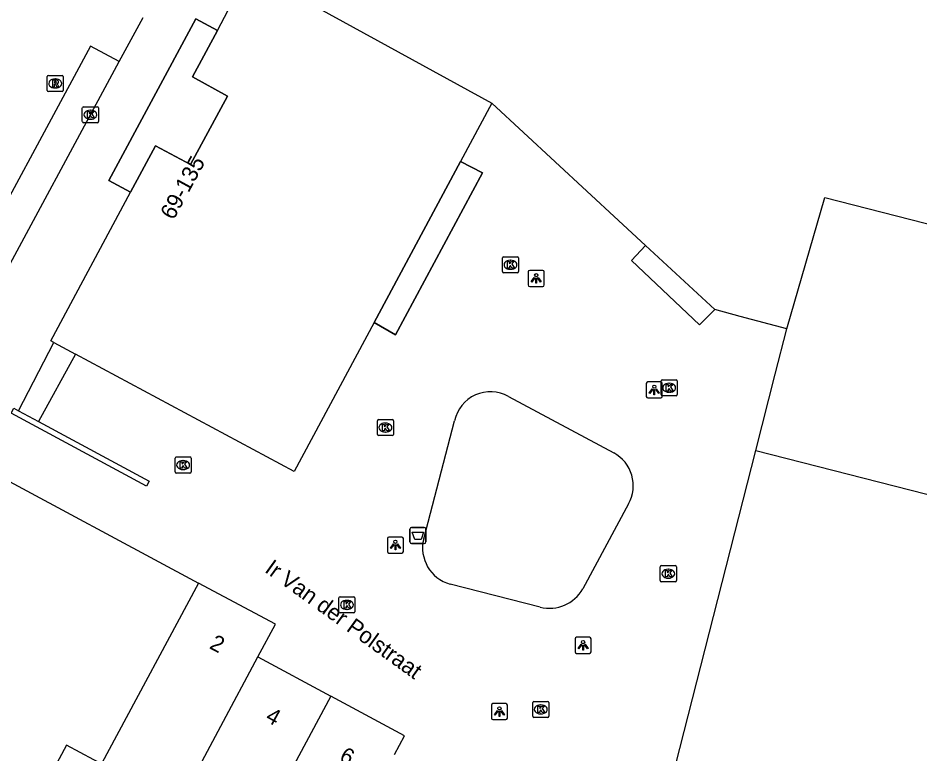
# Model space of a CAD drawing. Extents: x 159489 to 160304, y 383826 to 384530.
# Drawn here: x 159768.9 to 159824.9, y 384093.2 to 384138.9 of the extents above; entities that cross this region are included whole.
import ezdxf

# ---------------------------------------------------------------- set-up
doc = ezdxf.new("R2010")
doc.units = 0
for name, color, linetype in [('IMGEO_Afvalbak', 7, 'Continuous'), ('IMGEO_Kolk', 7, 'Continuous'), ('IMGEO_Lichtpunt', 7, 'Continuous'), ('IMGEO_Muur', 7, 'Continuous'), ('IMGEO_Openbare_ruimte_label', 7, 'Continuous'), ('IMGEO_Pand', 7, 'Continuous'), ('IMGEO_Pand_nummerreeks', 7, 'Continuous'), ('IMGEO_Pand_overbouw', 7, 'Continuous'), ('IMGEO_Rijbaan_lokaal_gesloten', 7, 'Continuous'), ('IMGEO_Rioolput', 7, 'Continuous'), ('IMGEO_Voetpad_open', 7, 'Continuous')]:
    doc.layers.add(name, color=color, linetype=linetype)

msp = doc.modelspace()

# ---------------------------------------------------------------- linework, layer by layer
at = {"layer": 'IMGEO_Afvalbak'}
for p, q in [((159793.2, 384106.378), (159793.2, 384107.178)), ((159793.2, 384107.178), (159793.2, 384106.378)), ((159793.3, 384107.278), (159794.09, 384107.278)), ((159794.09, 384107.278), (159793.3, 384107.278)), ((159794.19, 384107.178), (159794.19, 384106.378)), ((159794.19, 384106.378), (159794.19, 384107.178)), ((159794.09, 384106.278), (159793.3, 384106.278)), ((159793.3, 384106.278), (159794.09, 384106.278))]:
    msp.add_line(p, q, dxfattribs=at)
msp.add_lwpolyline([(159793.343, 384106.992), (159794.047, 384106.992), (159793.898, 384106.522), (159793.492, 384106.522), (159793.343, 384106.992)], dxfattribs=at)
for centre, start, end in [((159793.3, 384107.178), 90, 180), ((159793.3, 384107.178), 90, 180), ((159794.09, 384107.178), 0, 90), ((159794.09, 384107.178), 360, 90), ((159793.3, 384106.378), 180, 270), ((159793.3, 384106.378), 180, 270), ((159794.09, 384106.378), 270, 0), ((159794.09, 384106.378), 270, 0)]:
    msp.add_arc(centre, 0.1, start, end, dxfattribs=at)
at = {"layer": 'IMGEO_Kolk'}
for p, q in [((159772.86, 384132.46), (159772.86, 384133.312)), ((159772.935, 384133.386), (159773.787, 384133.386)), ((159773.861, 384133.312), (159773.861, 384132.46)), ((159773.348, 384133.166), (159773.373, 384133.166)), ((159773.787, 384132.386), (159772.935, 384132.386)), ((159773.371, 384132.606), (159773.346, 384132.606)), ((159798.939, 384123.15), (159798.939, 384124.002)), ((159799.014, 384124.076), (159799.866, 384124.076)), ((159799.427, 384123.856), (159799.452, 384123.856)), ((159799.94, 384124.002), (159799.94, 384123.15)), ((159799.45, 384123.296), (159799.425, 384123.296)), ((159799.866, 384123.076), (159799.014, 384123.076)), ((159808.791, 384115.518), (159808.791, 384116.37)), ((159808.866, 384116.444), (159809.718, 384116.444)), ((159809.279, 384116.224), (159809.304, 384116.224)), ((159809.792, 384116.37), (159809.792, 384115.518)), ((159809.718, 384115.444), (159808.866, 384115.444)), ((159809.302, 384115.664), (159809.277, 384115.664)), ((159791.175, 384113.049), (159791.175, 384113.901)), ((159791.25, 384113.975), (159792.102, 384113.975)), ((159791.663, 384113.755), (159791.688, 384113.755)), ((159792.176, 384113.901), (159792.176, 384113.049)), ((159791.686, 384113.195), (159791.661, 384113.195)), ((159792.102, 384112.975), (159791.25, 384112.975)), ((159778.616, 384110.723), (159778.616, 384111.575)), ((159778.691, 384111.649), (159779.543, 384111.649)), ((159779.104, 384111.429), (159779.129, 384111.429)), ((159779.617, 384111.575), (159779.617, 384110.723)), ((159779.127, 384110.869), (159779.102, 384110.869)), ((159779.543, 384110.649), (159778.691, 384110.649)), ((159808.737, 384103.981), (159808.737, 384104.833)), ((159808.812, 384104.907), (159809.664, 384104.907)), ((159809.738, 384104.833), (159809.738, 384103.981)), ((159809.225, 384104.687), (159809.25, 384104.687)), ((159809.664, 384103.907), (159808.812, 384103.907)), ((159809.248, 384104.127), (159809.223, 384104.127)), ((159788.785, 384102.048), (159788.785, 384102.9)), ((159788.86, 384102.974), (159789.712, 384102.974)), ((159789.273, 384102.754), (159789.298, 384102.754)), ((159789.786, 384102.9), (159789.786, 384102.048)), ((159789.712, 384101.974), (159788.86, 384101.974)), ((159789.296, 384102.194), (159789.271, 384102.194)), ((159800.819, 384095.561), (159800.819, 384096.413)), ((159800.894, 384096.487), (159801.746, 384096.487)), ((159801.82, 384096.413), (159801.82, 384095.561)), ((159801.307, 384096.267), (159801.332, 384096.267)), ((159801.746, 384095.487), (159800.894, 384095.487)), ((159801.33, 384095.707), (159801.305, 384095.707))]:
    msp.add_line(p, q, dxfattribs=at)
for points in [[(159772.86, 384132.46), (159772.86, 384133.312)], [(159772.935, 384133.386), (159773.787, 384133.386)], [(159773.861, 384133.312), (159773.861, 384132.46)], [(159773.181, 384133.086), (159773.304, 384133.086), (159773.304, 384132.935), (159773.434, 384133.086), (159773.598, 384133.086), (159773.452, 384132.935), (159773.605, 384132.686), (159773.453, 384132.686), (159773.368, 384132.85), (159773.304, 384132.783), (159773.304, 384132.686), (159773.181, 384132.686), (159773.181, 384133.086)], [(159773.787, 384132.386), (159772.935, 384132.386)], [(159798.939, 384123.15), (159798.939, 384124.002)], [(159799.014, 384124.076), (159799.866, 384124.076)], [(159799.26, 384123.776), (159799.383, 384123.776), (159799.383, 384123.625), (159799.513, 384123.776), (159799.677, 384123.776), (159799.531, 384123.625), (159799.684, 384123.376), (159799.532, 384123.376), (159799.447, 384123.54), (159799.383, 384123.473), (159799.383, 384123.376), (159799.26, 384123.376), (159799.26, 384123.776)], [(159799.94, 384124.002), (159799.94, 384123.15)], [(159799.866, 384123.076), (159799.014, 384123.076)], [(159808.791, 384115.518), (159808.791, 384116.37)], [(159808.866, 384116.444), (159809.718, 384116.444)], [(159809.112, 384116.144), (159809.235, 384116.144), (159809.235, 384115.993), (159809.365, 384116.144), (159809.529, 384116.144), (159809.383, 384115.993), (159809.536, 384115.744), (159809.384, 384115.744), (159809.299, 384115.908), (159809.235, 384115.841), (159809.235, 384115.744), (159809.112, 384115.744), (159809.112, 384116.144)], [(159809.792, 384116.37), (159809.792, 384115.518)], [(159809.718, 384115.444), (159808.866, 384115.444)], [(159791.175, 384113.049), (159791.175, 384113.901)], [(159791.25, 384113.975), (159792.102, 384113.975)], [(159791.496, 384113.675), (159791.619, 384113.675), (159791.619, 384113.524), (159791.749, 384113.675), (159791.913, 384113.675), (159791.767, 384113.524), (159791.92, 384113.275), (159791.768, 384113.275), (159791.683, 384113.439), (159791.619, 384113.372), (159791.619, 384113.275), (159791.496, 384113.275), (159791.496, 384113.675)], [(159792.176, 384113.901), (159792.176, 384113.049)], [(159792.102, 384112.975), (159791.25, 384112.975)], [(159778.616, 384110.723), (159778.616, 384111.575)], [(159778.691, 384111.649), (159779.543, 384111.649)], [(159779.617, 384111.575), (159779.617, 384110.723)], [(159778.937, 384111.349), (159779.06, 384111.349), (159779.06, 384111.198), (159779.19, 384111.349), (159779.354, 384111.349), (159779.208, 384111.198), (159779.361, 384110.949), (159779.209, 384110.949), (159779.124, 384111.113), (159779.06, 384111.046), (159779.06, 384110.949), (159778.937, 384110.949), (159778.937, 384111.349)], [(159779.543, 384110.649), (159778.691, 384110.649)], [(159808.737, 384103.981), (159808.737, 384104.833)], [(159808.812, 384104.907), (159809.664, 384104.907)], [(159809.738, 384104.833), (159809.738, 384103.981)], [(159809.058, 384104.607), (159809.181, 384104.607), (159809.181, 384104.456), (159809.311, 384104.607), (159809.475, 384104.607), (159809.329, 384104.456), (159809.482, 384104.207), (159809.33, 384104.207), (159809.245, 384104.371), (159809.181, 384104.304), (159809.181, 384104.207), (159809.058, 384104.207), (159809.058, 384104.607)], [(159809.664, 384103.907), (159808.812, 384103.907)], [(159788.785, 384102.048), (159788.785, 384102.9)], [(159788.86, 384102.974), (159789.712, 384102.974)], [(159789.106, 384102.674), (159789.229, 384102.674), (159789.229, 384102.523), (159789.359, 384102.674), (159789.523, 384102.674), (159789.377, 384102.523), (159789.53, 384102.274), (159789.378, 384102.274), (159789.293, 384102.438), (159789.229, 384102.371), (159789.229, 384102.274), (159789.106, 384102.274), (159789.106, 384102.674)], [(159789.786, 384102.9), (159789.786, 384102.048)], [(159789.712, 384101.974), (159788.86, 384101.974)], [(159800.819, 384095.561), (159800.819, 384096.413)], [(159800.894, 384096.487), (159801.746, 384096.487)], [(159801.82, 384096.413), (159801.82, 384095.561)], [(159801.14, 384096.187), (159801.263, 384096.187), (159801.263, 384096.036), (159801.393, 384096.187), (159801.557, 384096.187), (159801.411, 384096.036), (159801.564, 384095.787), (159801.412, 384095.787), (159801.327, 384095.951), (159801.263, 384095.884), (159801.263, 384095.787), (159801.14, 384095.787), (159801.14, 384096.187)], [(159801.746, 384095.487), (159800.894, 384095.487)]]:
    msp.add_lwpolyline(points, dxfattribs=at)
for centre, start, end in [((159772.937, 384133.31), 91.552, 178.448), ((159772.937, 384133.31), 91.552, 178.448), ((159773.785, 384133.31), 1.552, 88.448), ((159773.785, 384133.31), 1.552, 88.448), ((159772.937, 384132.462), 181.552, 268.448), ((159772.937, 384132.462), 181.552, 268.448), ((159773.785, 384132.462), 271.552, 358.448), ((159773.785, 384132.462), 271.552, 358.448), ((159799.016, 384124), 91.552, 178.448), ((159799.016, 384124), 91.552, 178.448), ((159799.864, 384124), 1.552, 88.448), ((159799.864, 384124), 1.552, 88.448), ((159799.016, 384123.152), 181.552, 268.448), ((159799.016, 384123.152), 181.552, 268.448), ((159799.864, 384123.152), 271.552, 358.448), ((159799.864, 384123.152), 271.552, 358.448), ((159808.868, 384116.368), 91.552, 178.448), ((159808.868, 384116.368), 91.552, 178.448), ((159809.716, 384116.368), 1.552, 88.448), ((159809.716, 384116.368), 1.552, 88.448), ((159808.868, 384115.52), 181.552, 268.448), ((159808.868, 384115.52), 181.552, 268.448), ((159809.716, 384115.52), 271.552, 358.448), ((159809.716, 384115.52), 271.552, 358.448), ((159791.252, 384113.899), 91.552, 178.448), ((159791.252, 384113.899), 91.552, 178.448), ((159792.1, 384113.899), 1.552, 88.448), ((159792.1, 384113.899), 1.552, 88.448), ((159791.252, 384113.051), 181.552, 268.448), ((159791.252, 384113.051), 181.552, 268.448), ((159792.1, 384113.051), 271.552, 358.448), ((159792.1, 384113.051), 271.552, 358.448), ((159778.693, 384111.573), 91.552, 178.448), ((159778.693, 384111.573), 91.552, 178.448), ((159779.541, 384111.573), 1.552, 88.448), ((159779.541, 384111.573), 1.552, 88.448), ((159778.693, 384110.725), 181.552, 268.448), ((159778.693, 384110.725), 181.552, 268.448), ((159779.541, 384110.725), 271.552, 358.448), ((159779.541, 384110.725), 271.552, 358.448), ((159808.814, 384104.831), 91.552, 178.448), ((159808.814, 384104.831), 91.552, 178.448), ((159809.662, 384104.831), 1.552, 88.448), ((159809.662, 384104.831), 1.552, 88.448), ((159808.814, 384103.983), 181.552, 268.448), ((159808.814, 384103.983), 181.552, 268.448), ((159809.662, 384103.983), 271.552, 358.448), ((159809.662, 384103.983), 271.552, 358.448), ((159788.862, 384102.898), 91.552, 178.448), ((159788.862, 384102.898), 91.552, 178.448), ((159789.71, 384102.898), 1.552, 88.448), ((159789.71, 384102.898), 1.552, 88.448), ((159788.862, 384102.05), 181.552, 268.448), ((159788.862, 384102.05), 181.552, 268.448), ((159789.71, 384102.05), 271.552, 358.448), ((159789.71, 384102.05), 271.552, 358.448), ((159800.896, 384096.411), 91.552, 178.448), ((159800.896, 384096.411), 91.552, 178.448), ((159801.744, 384096.411), 1.552, 88.448), ((159801.744, 384096.411), 1.552, 88.448), ((159800.896, 384095.563), 181.552, 268.448), ((159800.896, 384095.563), 181.552, 268.448), ((159801.744, 384095.563), 271.552, 358.448), ((159801.744, 384095.563), 271.552, 358.448)]:
    msp.add_arc(centre, 0.0765, start, end, dxfattribs=at)
for centre, major_axis, ratio, start_param, end_param in [((159773.347, 384132.886), (-0.387, 0.002), 0.722429, 4.712389, 7.853982), ((159773.372, 384132.886), (-0.39, 0.002), 0.717154, 1.570796, 4.712389), ((159799.426, 384123.576), (-0.387, 0.002), 0.722429, 4.712389, 7.853982), ((159799.451, 384123.576), (-0.39, 0.002), 0.717154, 1.570796, 4.712389), ((159809.278, 384115.944), (-0.387, 0.002), 0.722429, 4.712389, 7.853982), ((159809.303, 384115.944), (-0.39, 0.002), 0.717154, 1.570796, 4.712389), ((159791.662, 384113.475), (-0.387, 0.002), 0.722429, 4.712389, 7.853982), ((159791.687, 384113.475), (-0.39, 0.002), 0.717154, 1.570796, 4.712389), ((159779.103, 384111.149), (-0.387, 0.002), 0.722429, 4.712389, 7.853982), ((159779.128, 384111.149), (-0.39, 0.002), 0.717154, 1.570796, 4.712389), ((159809.224, 384104.407), (-0.387, 0.002), 0.722429, 4.712389, 7.853982), ((159809.249, 384104.407), (-0.39, 0.002), 0.717154, 1.570796, 4.712389), ((159789.272, 384102.474), (-0.387, 0.002), 0.722429, 4.712389, 7.853982), ((159789.297, 384102.474), (-0.39, 0.002), 0.717154, 1.570796, 4.712389), ((159801.306, 384095.987), (-0.387, 0.002), 0.722429, 4.712389, 7.853982), ((159801.331, 384095.987), (-0.39, 0.002), 0.717154, 1.570796, 4.712389)]:
    msp.add_ellipse(centre, major_axis=major_axis, ratio=ratio, start_param=start_param, end_param=end_param, dxfattribs=at)
at = {"layer": 'IMGEO_Lichtpunt'}
for p, q in [((159801.44, 384123.228), (159800.632, 384123.228)), ((159801.44, 384123.228), (159800.632, 384123.228)), ((159800.538, 384123.133), (159800.538, 384122.326)), ((159800.538, 384123.133), (159800.538, 384122.326)), ((159801.534, 384122.326), (159801.534, 384123.133)), ((159801.534, 384122.326), (159801.534, 384123.133)), ((159800.632, 384122.232), (159801.44, 384122.232)), ((159800.632, 384122.232), (159801.44, 384122.232)), ((159807.867, 384116.215), (159807.867, 384115.408)), ((159807.867, 384116.215), (159807.867, 384115.408)), ((159808.769, 384116.31), (159807.961, 384116.31)), ((159808.769, 384116.31), (159807.961, 384116.31)), ((159808.863, 384115.408), (159808.863, 384116.215)), ((159808.863, 384115.408), (159808.863, 384116.215)), ((159807.961, 384115.314), (159808.769, 384115.314)), ((159807.961, 384115.314), (159808.769, 384115.314)), ((159791.796, 384106.589), (159791.796, 384105.782)), ((159791.796, 384106.589), (159791.796, 384105.782)), ((159792.698, 384106.684), (159791.89, 384106.684)), ((159792.698, 384106.684), (159791.89, 384106.684)), ((159792.792, 384105.782), (159792.792, 384106.589)), ((159792.792, 384105.782), (159792.792, 384106.589)), ((159791.89, 384105.688), (159792.698, 384105.688)), ((159791.89, 384105.688), (159792.698, 384105.688)), ((159803.447, 384100.366), (159803.447, 384099.559)), ((159803.447, 384100.366), (159803.447, 384099.559)), ((159804.349, 384100.461), (159803.541, 384100.461)), ((159804.349, 384100.461), (159803.541, 384100.461)), ((159804.443, 384099.559), (159804.443, 384100.366)), ((159804.443, 384099.559), (159804.443, 384100.366)), ((159803.541, 384099.465), (159804.349, 384099.465)), ((159803.541, 384099.465), (159804.349, 384099.465)), ((159799.155, 384096.35), (159798.347, 384096.35)), ((159799.155, 384096.35), (159798.347, 384096.35)), ((159798.253, 384096.255), (159798.253, 384095.448)), ((159798.253, 384096.255), (159798.253, 384095.448)), ((159799.249, 384095.448), (159799.249, 384096.255)), ((159799.249, 384095.448), (159799.249, 384096.255)), ((159798.347, 384095.354), (159799.155, 384095.354)), ((159798.347, 384095.354), (159799.155, 384095.354))]:
    msp.add_line(p, q, dxfattribs=at)
for points in [[(159800.912, 384122.797), (159800.951, 384122.769), (159800.763, 384122.507), (159800.725, 384122.534), (159800.912, 384122.797)], [(159801.014, 384122.749), (159801.061, 384122.749), (159801.061, 384122.427), (159801.014, 384122.427), (159801.014, 384122.749)], [(159801.124, 384122.769), (159801.162, 384122.796), (159801.349, 384122.534), (159801.31, 384122.506), (159801.124, 384122.769)], [(159808.241, 384115.879), (159808.28, 384115.851), (159808.092, 384115.589), (159808.054, 384115.616), (159808.241, 384115.879)], [(159808.343, 384115.831), (159808.39, 384115.831), (159808.39, 384115.509), (159808.343, 384115.509), (159808.343, 384115.831)], [(159808.453, 384115.851), (159808.491, 384115.878), (159808.678, 384115.616), (159808.639, 384115.588), (159808.453, 384115.851)], [(159792.17, 384106.253), (159792.209, 384106.225), (159792.021, 384105.963), (159791.983, 384105.99), (159792.17, 384106.253)], [(159792.272, 384106.205), (159792.319, 384106.205), (159792.319, 384105.883), (159792.272, 384105.883), (159792.272, 384106.205)], [(159792.382, 384106.225), (159792.42, 384106.252), (159792.607, 384105.99), (159792.568, 384105.962), (159792.382, 384106.225)], [(159803.821, 384100.03), (159803.86, 384100.002), (159803.672, 384099.74), (159803.634, 384099.767), (159803.821, 384100.03)], [(159803.923, 384099.982), (159803.97, 384099.982), (159803.97, 384099.66), (159803.923, 384099.66), (159803.923, 384099.982)], [(159804.033, 384100.002), (159804.071, 384100.029), (159804.258, 384099.767), (159804.219, 384099.739), (159804.033, 384100.002)], [(159798.627, 384095.919), (159798.666, 384095.891), (159798.478, 384095.629), (159798.44, 384095.656), (159798.627, 384095.919)], [(159798.729, 384095.871), (159798.776, 384095.871), (159798.776, 384095.549), (159798.729, 384095.549), (159798.729, 384095.871)], [(159798.839, 384095.891), (159798.877, 384095.918), (159799.064, 384095.656), (159799.025, 384095.628), (159798.839, 384095.891)]]:
    msp.add_lwpolyline(points, dxfattribs=at)
for centre in [(159801.037, 384122.931), (159808.366, 384116.013), (159792.295, 384106.387), (159803.946, 384100.164), (159798.752, 384096.053)]:
    msp.add_circle(centre, 0.0994, dxfattribs=at)
for centre, start, end in [((159800.632, 384123.133), 90, 180), ((159800.632, 384123.133), 90, 180), ((159801.44, 384123.133), 0, 90), ((159801.44, 384123.133), 0, 90), ((159800.632, 384122.326), 180, 270), ((159800.632, 384122.326), 180, 270), ((159801.44, 384122.326), 270, 0), ((159801.44, 384122.326), 270, 360), ((159807.961, 384116.215), 90, 180), ((159807.961, 384116.215), 90, 180), ((159808.769, 384116.215), 0, 90), ((159808.769, 384116.215), 0, 90), ((159807.961, 384115.408), 180, 270), ((159807.961, 384115.408), 180, 270), ((159808.769, 384115.408), 270, 0), ((159808.769, 384115.408), 270, 360), ((159791.89, 384106.589), 90, 180), ((159791.89, 384106.589), 90, 180), ((159792.698, 384106.589), 0, 90), ((159792.698, 384106.589), 0, 90), ((159791.89, 384105.782), 180, 270), ((159791.89, 384105.782), 180, 270), ((159792.698, 384105.782), 270, 0), ((159792.698, 384105.782), 270, 360), ((159803.541, 384100.366), 90, 180), ((159803.541, 384100.366), 90, 180), ((159804.349, 384100.366), 0, 90), ((159804.349, 384100.366), 0, 90), ((159803.541, 384099.559), 180, 270), ((159803.541, 384099.559), 180, 270), ((159804.349, 384099.559), 270, 0), ((159804.349, 384099.559), 270, 360), ((159798.347, 384096.255), 90, 180), ((159798.347, 384096.255), 90, 180), ((159799.155, 384096.255), 0, 90), ((159799.155, 384096.255), 0, 90), ((159798.347, 384095.448), 180, 270), ((159798.347, 384095.448), 180, 270), ((159799.155, 384095.448), 270, 0), ((159799.155, 384095.448), 270, 360)]:
    msp.add_arc(centre, 0.0946, start, end, dxfattribs=at)
at = {"layer": 'IMGEO_Muur'}
for points in [[(159768.446, 384114.365), (159768.611, 384114.673), (159768.906, 384114.514)], [(159770.147, 384113.845), (159777.002, 384110.151), (159776.835, 384109.843), (159768.446, 384114.365)], [(159768.906, 384114.514), (159770.147, 384113.845)]]:
    msp.add_lwpolyline(points, dxfattribs=at)
at = {"layer": 'IMGEO_Pand'}
for points in [[(159781.249, 384138.115), (159783.227, 384141.884)], [(159783.227, 384141.884), (159798.285, 384133.608)], [(159781.249, 384138.115), (159779.704, 384135.243), (159781.88, 384134.044), (159779.568, 384129.802), (159777.398, 384130.962), (159775.853, 384128.086)], [(159798.285, 384133.608), (159796.346, 384129.995)], [(159807.826, 384124.77), (159806.143, 384126.329), (159798.285, 384133.608)], [(159790.975, 384119.986), (159796.346, 384129.995)], [(159771.098, 384118.744), (159770.9, 384118.851), (159775.853, 384128.086)], [(159816.6, 384119.612), (159818.956, 384127.743), (159834.974, 384123.654)], [(159807.826, 384124.77), (159812.12, 384120.793)], [(159816.6, 384119.612), (159813.7, 384120.358), (159812.12, 384120.793)], [(159790.975, 384119.986), (159786.016, 384110.746), (159772.445, 384118.022)], [(159814.676, 384112.061), (159815.881, 384116.79), (159816.6, 384119.612)], [(159771.098, 384118.744), (159772.445, 384118.022)], [(159815.417, 384087.11), (159809.159, 384090.473), (159814.676, 384112.061)], [(159814.676, 384112.061), (159830.962, 384107.902)], [(159766.66, 384111.026), (159780.079, 384103.825)], [(159780.079, 384103.825), (159774.383, 384093.224), (159774.052, 384092.608), (159773.584, 384092.86)], [(159783.759, 384099.239), (159784.844, 384101.268), (159780.079, 384103.825)], [(159778.243, 384088.92), (159779.168, 384090.651), (159783.759, 384099.239)], [(159783.759, 384099.239), (159788.289, 384096.804)], [(159788.289, 384096.804), (159783.685, 384088.244), (159782.746, 384086.499)], [(159792.249, 384093.193), (159792.852, 384094.351), (159788.289, 384096.804)], [(159773.584, 384092.86), (159771.882, 384093.775), (159768.398, 384087.297), (159767.715, 384087.664)]]:
    msp.add_lwpolyline(points, dxfattribs=at)
at = {"layer": 'IMGEO_Pand_overbouw'}
for points in [[(159775.853, 384128.086), (159777.398, 384130.962), (159779.568, 384129.802), (159781.88, 384134.044), (159779.704, 384135.243), (159781.249, 384138.115), (159779.906, 384138.843), (159774.496, 384128.807)], [(159790.975, 384119.986), (159792.304, 384119.236), (159797.698, 384129.277), (159796.346, 384129.995)]]:
    msp.add_lwpolyline(points, close=True, dxfattribs=at)
at = {"layer": 'IMGEO_Rijbaan_lokaal_gesloten'}
for points in [[(159775.147, 384136.187), (159776.629, 384138.93)], [(159775.147, 384136.187), (159773.371, 384137.146), (159765.302, 384122.213), (159767.077, 384121.254)]]:
    msp.add_lwpolyline(points, dxfattribs=at)
at = {"layer": 'IMGEO_Rioolput'}
for p, q in [((159770.678, 384134.4), (159770.678, 384135.252)), ((159770.753, 384135.326), (159771.605, 384135.326)), ((159771.166, 384135.106), (159771.191, 384135.106)), ((159771.679, 384135.252), (159771.679, 384134.4)), ((159771.189, 384134.546), (159771.164, 384134.546)), ((159771.605, 384134.326), (159770.753, 384134.326))]:
    msp.add_line(p, q, dxfattribs=at)
for points in [[(159770.678, 384134.4), (159770.678, 384135.252)], [(159770.753, 384135.326), (159771.605, 384135.326)], [(159771.267, 384135.024), (159771.015, 384135.026), (159771.015, 384134.626)], [(159771.193, 384134.945), (159771.139, 384134.945), (159771.139, 384134.864)], [(159771.679, 384135.252), (159771.679, 384134.4)], [(159771.015, 384134.626), (159771.139, 384134.626), (159771.139, 384134.788), (159771.15, 384134.788)], [(159771.139, 384134.864), (159771.191, 384134.864)], [(159771.197, 384134.759), (159771.268, 384134.626), (159771.408, 384134.626), (159771.343, 384134.752)], [(159771.605, 384134.326), (159770.753, 384134.326)]]:
    msp.add_lwpolyline(points, dxfattribs=at)
for centre, radius, start, end in [((159770.755, 384135.25), 0.0765, 91.552, 178.448), ((159770.755, 384135.25), 0.0765, 91.552, 178.448), ((159771.199, 384134.849), 0.0964, 77.0061, 93.1865), ((159771.213, 384134.906), 0.0378, 276.6634, 79.6772), ((159771.266, 384134.914), 0.109, 350.3612, 89.416), ((159771.603, 384135.25), 0.0765, 1.552, 88.448), ((159771.603, 384135.25), 0.0765, 1.552, 88.448), ((159770.755, 384134.402), 0.0765, 181.552, 268.448), ((159770.755, 384134.402), 0.0765, 181.552, 268.448), ((159771.149, 384134.735), 0.0533, 26.0293, 88.6989), ((159771.175, 384135.053), 0.19, 274.7715, 282.9687), ((159771.264, 384134.914), 0.112, 277.5842, 350.9817), ((159771.248, 384134.699), 0.108, 29.5134, 73.7905), ((159771.603, 384134.402), 0.0765, 271.552, 358.448), ((159771.603, 384134.402), 0.0765, 271.552, 358.448)]:
    msp.add_arc(centre, radius, start, end, dxfattribs=at)
for centre, major_axis, ratio, start_param, end_param in [((159771.165, 384134.826), (-0.387, 0.002), 0.722429, 4.712389, 7.853982), ((159771.19, 384134.826), (-0.39, 0.002), 0.717154, 1.570796, 4.712389)]:
    msp.add_ellipse(centre, major_axis=major_axis, ratio=ratio, start_param=start_param, end_param=end_param, dxfattribs=at)
at = {"layer": 'IMGEO_Voetpad_open'}
for points in [[(159775.853, 384128.086), (159774.496, 384128.807), (159779.906, 384138.843), (159781.249, 384138.115)], [(159767.077, 384121.254), (159775.147, 384136.187)], [(159796.346, 384129.995), (159797.698, 384129.277), (159792.304, 384119.236), (159790.975, 384119.986)], [(159812.12, 384120.793), (159811.179, 384119.845), (159806.946, 384123.837), (159807.826, 384124.77)], [(159768.906, 384114.514), (159771.098, 384118.744)], [(159772.445, 384118.022), (159770.147, 384113.845)], [(159799.312, 384115.406), (159805.852, 384111.908)], [(159794.052, 384106.576), (159795.969, 384113.899)], [(159806.774, 384108.74), (159803.924, 384103.465)], [(159801.284, 384102.333), (159795.687, 384103.761)]]:
    msp.add_lwpolyline(points, dxfattribs=at)
for centre, radius, start, end in [((159798.195, 384113.423), 2.276, 60.5947, 167.9364), ((159804.736, 384109.865), 2.328, 331.1022, 61.3515), ((159796.32, 384106.011), 2.338, 166.0161, 254.2814), ((159801.862, 384104.63), 2.368, 255.8778, 330.5404)]:
    msp.add_arc(centre, radius, start, end, dxfattribs=at)

# ---------------------------------------------------------------- texts
at = {"layer": 'IMGEO_Openbare_ruimte_label'}
msp.add_text('Ir Van der Polstraat', height=1, rotation=324.2759, dxfattribs=at).set_placement((159784.122, 384104.549))
at = {"layer": 'IMGEO_Pand_nummerreeks'}
for s, rotation, p in [('69-135', 61.3972, (159778.522, 384126.305)), ('2', 332.1371, (159780.691, 384099.802)), ('4', 331.312, (159784.166, 384095.297)), ('6', 332.3204, (159788.751, 384092.823))]:
    msp.add_text(s, height=1, rotation=rotation, dxfattribs=at).set_placement(p)

doc.saveas('drawing.dxf')
